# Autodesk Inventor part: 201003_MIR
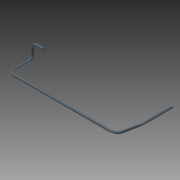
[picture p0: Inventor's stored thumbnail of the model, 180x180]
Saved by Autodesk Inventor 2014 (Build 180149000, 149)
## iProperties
Created: 2007-12
Part Number: 201003_MIR
Material: Steel
Description: SIDE MOUNTING BAR
Document SubType Name: Modeling
Designer: jjohnson
Mass: 75.8289 g
Surface Area: 77.6706 cm^2
Volume: 9.65974 cm^3
Density: 7.85 g/cm^3
Appearance: Lead
Component Category: Lower Component
Author: MM
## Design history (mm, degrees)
node "201003"
  sketch "Sketch2"
    geometry: L1 (0, 0)-(60, -50) reference; L2 (60, -50)-(310, -50) reference; L3 (310, 10)-(310, -60) reference; 3 further points
  sketch "Sketch3"
    geometry: L1 (50, -70)-(50, -15) reference; L2 (50, -15)-(17.5, -15) reference; 2 further points
  sketch "Sketch4"
    geometry: L1 (0, 0)-(25, 0) reference; 1 further point
  sketch "Sketch5"
    geometry: C1 r 2.5 at (0, 0) reference; 1 further point
  workplane "Work Plane1"
  workplane "Work Plane2"
  workplane "Work Plane3"
body "Solid1"
tag "TaggingFeature2"
workplane "Work Plane4"
feature "DerivedBody::D-201003.ipt"
